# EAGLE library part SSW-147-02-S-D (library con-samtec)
THROUGH-HOLE .025" SQ POST SOCKET Source: Samtec SSW.pdf
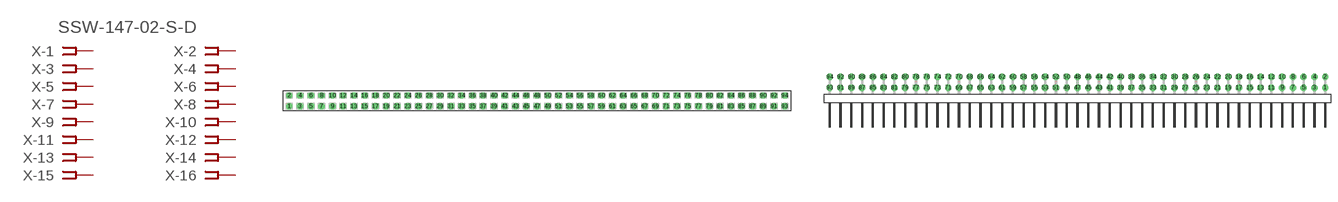
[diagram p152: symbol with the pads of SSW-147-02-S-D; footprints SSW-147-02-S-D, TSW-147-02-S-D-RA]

Designator prefix X; gates -1=FPINV -2=FPIN -3=FPIN -4=FPIN -5=FPIN -6=FPIN -7=FPIN -8=FPIN -9=FPIN -10=FPIN -11=FPIN -12=FPIN -13=FPIN -14=FPIN -15=FPIN -16=FPIN -17=FPIN -18=FPIN -19=FPIN -20=FPIN -21=FPIN -22=FPIN -23=FPIN -24=FPIN -25=FPIN -26=FPIN -27=FPIN -28=FPIN -29=FPIN -30=FPIN -31=FPIN -32=FPIN -33=FPIN -34=FPIN -35=FPIN -36=FPIN -37=FPIN -38=FPIN -39=FPIN -40=FPIN -41=FPIN -42=FPIN -43=FPIN -44=FPIN -45=FPIN -46=FPIN -47=FPIN -48=FPIN -49=FPIN -50=FPIN -51=FPIN -52=FPIN -53=FPIN -54=FPIN -55=FPIN -56=FPIN -57=FPIN -58=FPIN -59=FPIN -60=FPIN -61=FPIN -62=FPIN -63=FPIN -64=FPIN -65=FPIN -66=FPIN -67=FPIN -68=FPIN -69=FPIN -70=FPIN -71=FPIN -72=FPIN -73=FPIN -74=FPIN -75=FPIN -76=FPIN -77=FPIN -78=FPIN -79=FPIN -80=FPIN -81=FPIN -82=FPIN -83=FPIN -84=FPIN -85=FPIN -86=FPIN -87=FPIN -88=FPIN -89=FPIN -90=FPIN -91=FPIN -92=FPIN -93=FPIN -94=FPIN

## SSW-147-02-S-D (OC_FARNELL: unknown; OC_NEWARK: unknown)  [SSW-147-02-S-D]
1  -1:1  pas
2  -2:1  pas
3  -3:1  pas
4  -4:1  pas
5  -5:1  pas
6  -6:1  pas
7  -7:1  pas
8  -8:1  pas
9  -9:1  pas
10  -10:1  pas
11  -11:1  pas
12  -12:1  pas
13  -13:1  pas
14  -14:1  pas
15  -15:1  pas
16  -16:1  pas
17  -17:1  pas
18  -18:1  pas
19  -19:1  pas
20  -20:1  pas
21  -21:1  pas
22  -22:1  pas
23  -23:1  pas
24  -24:1  pas
25  -25:1  pas
26  -26:1  pas
27  -27:1  pas
28  -28:1  pas
29  -29:1  pas
30  -30:1  pas
31  -31:1  pas
32  -32:1  pas
33  -33:1  pas
34  -34:1  pas
35  -35:1  pas
36  -36:1  pas
37  -37:1  pas
38  -38:1  pas
39  -39:1  pas
40  -40:1  pas
41  -41:1  pas
42  -42:1  pas
43  -43:1  pas
44  -44:1  pas
45  -45:1  pas
46  -46:1  pas
47  -47:1  pas
48  -48:1  pas
49  -49:1  pas
50  -50:1  pas
51  -51:1  pas
52  -52:1  pas
53  -53:1  pas
54  -54:1  pas
55  -55:1  pas
56  -56:1  pas
57  -57:1  pas
58  -58:1  pas
59  -59:1  pas
60  -60:1  pas
61  -61:1  pas
62  -62:1  pas
63  -63:1  pas
64  -64:1  pas
65  -65:1  pas
66  -66:1  pas
67  -67:1  pas
68  -68:1  pas
69  -69:1  pas
70  -70:1  pas
71  -71:1  pas
72  -72:1  pas
73  -73:1  pas
74  -74:1  pas
75  -75:1  pas
76  -76:1  pas
77  -77:1  pas
78  -78:1  pas
79  -79:1  pas
80  -80:1  pas
81  -81:1  pas
82  -82:1  pas
83  -83:1  pas
84  -84:1  pas
85  -85:1  pas
86  -86:1  pas
87  -87:1  pas
88  -88:1  pas
89  -89:1  pas
90  -90:1  pas
91  -91:1  pas
92  -92:1  pas
93  -93:1  pas
94  -94:1  pas

## SSW-147-02-S-D-RA (OC_FARNELL: unknown; OC_NEWARK: unknown)  [TSW-147-02-S-D-RA]
Pads as for SSW-147-02-S-D

## Footprint SSW-147-02-S-D (pad centres in mm)
THROUGH-HOLE .025" SQ POST SOCKET Source: Samtec SSW.pdf
drill 1 pad 1.5 octagon: 1 -58.42,-1.27; 2 -58.42,1.27; 3 -55.88,-1.27; 4 -55.88,1.27; 5 -53.34,-1.27; 6 -53.34,1.27; 7 -50.8,-1.27; 8 -50.8,1.27; 9 -48.26,-1.27; 10 -48.26,1.27; 11 -45.72,-1.27; 12 -45.72,1.27; 13 -43.18,-1.27; 14 -43.18,1.27; 15 -40.64,-1.27; 16 -40.64,1.27; 17 -38.1,-1.27; 18 -38.1,1.27; 19 -35.56,-1.27; 20 -35.56,1.27; 21 -33.02,-1.27; 22 -33.02,1.27; 23 -30.48,-1.27; 24 -30.48,1.27; 25 -27.94,-1.27; 26 -27.94,1.27; 27 -25.4,-1.27; 28 -25.4,1.27; 29 -22.86,-1.27; 30 -22.86,1.27; 31 -20.32,-1.27; 32 -20.32,1.27; 33 -17.78,-1.27; 34 -17.78,1.27; 35 -15.24,-1.27; 36 -15.24,1.27; 37 -12.7,-1.27; 38 -12.7,1.27; 39 -10.16,-1.27; 40 -10.16,1.27; 41 -7.62,-1.27; 42 -7.62,1.27; 43 -5.08,-1.27; 44 -5.08,1.27; 45 -2.54,-1.27; 46 -2.54,1.27; 47 0,-1.27; 48 0,1.27; 49 2.54,-1.27; 50 2.54,1.27; 51 5.08,-1.27; 52 5.08,1.27; 53 7.62,-1.27; 54 7.62,1.27; 55 10.16,-1.27; 56 10.16,1.27; 57 12.7,-1.27; 58 12.7,1.27; 59 15.24,-1.27; 60 15.24,1.27; 61 17.78,-1.27; 62 17.78,1.27; 63 20.32,-1.27; 64 20.32,1.27; 65 22.86,-1.27; 66 22.86,1.27; 67 25.4,-1.27; 68 25.4,1.27; 69 27.94,-1.27; 70 27.94,1.27; 71 30.48,-1.27; 72 30.48,1.27; 73 33.02,-1.27; 74 33.02,1.27; 75 35.56,-1.27; 76 35.56,1.27; 77 38.1,-1.27; 78 38.1,1.27; 79 40.64,-1.27; 80 40.64,1.27; 81 43.18,-1.27; 82 43.18,1.27; 83 45.72,-1.27; 84 45.72,1.27; 85 48.26,-1.27; 86 48.26,1.27; 87 50.8,-1.27; 88 50.8,1.27; 89 53.34,-1.27; 90 53.34,1.27; 91 55.88,-1.27; 92 55.88,1.27; 93 58.42,-1.27; 94 58.42,1.27

## Footprint TSW-147-02-S-D-RA (pad centres in mm)
THROUGH-HOLE .025" SQ POST HEADER Source: Samtec TSW.pdf
drill 1 pad 1.5 octagon: 1 58.42,1.524; 2 58.42,4.064; 3 55.88,1.524; 4 55.88,4.064; 5 53.34,1.524; 6 53.34,4.064; 7 50.8,1.524; 8 50.8,4.064; 9 48.26,1.524; 10 48.26,4.064; 11 45.72,1.524; 12 45.72,4.064; 13 43.18,1.524; 14 43.18,4.064; 15 40.64,1.524; 16 40.64,4.064; 17 38.1,1.524; 18 38.1,4.064; 19 35.56,1.524; 20 35.56,4.064; 21 33.02,1.524; 22 33.02,4.064; 23 30.48,1.524; 24 30.48,4.064; 25 27.94,1.524; 26 27.94,4.064; 27 25.4,1.524; 28 25.4,4.064; 29 22.86,1.524; 30 22.86,4.064; 31 20.32,1.524; 32 20.32,4.064; 33 17.78,1.524; 34 17.78,4.064; 35 15.24,1.524; 36 15.24,4.064; 37 12.7,1.524; 38 12.7,4.064; 39 10.16,1.524; 40 10.16,4.064; 41 7.62,1.524; 42 7.62,4.064; 43 5.08,1.524; 44 5.08,4.064; 45 2.54,1.524; 46 2.54,4.064; 47 0,1.524; 48 0,4.064; 49 -2.54,1.524; 50 -2.54,4.064; 51 -5.08,1.524; 52 -5.08,4.064; 53 -7.62,1.524; 54 -7.62,4.064; 55 -10.16,1.524; 56 -10.16,4.064; 57 -12.7,1.524; 58 -12.7,4.064; 59 -15.24,1.524; 60 -15.24,4.064; 61 -17.78,1.524; 62 -17.78,4.064; 63 -20.32,1.524; 64 -20.32,4.064; 65 -22.86,1.524; 66 -22.86,4.064; 67 -25.4,1.524; 68 -25.4,4.064; 69 -27.94,1.524; 70 -27.94,4.064; 71 -30.48,1.524; 72 -30.48,4.064; 73 -33.02,1.524; 74 -33.02,4.064; 75 -35.56,1.524; 76 -35.56,4.064; 77 -38.1,1.524; 78 -38.1,4.064; 79 -40.64,1.524; 80 -40.64,4.064; 81 -43.18,1.524; 82 -43.18,4.064; 83 -45.72,1.524; 84 -45.72,4.064; 85 -48.26,1.524; 86 -48.26,4.064; 87 -50.8,1.524; 88 -50.8,4.064; 89 -53.34,1.524; 90 -53.34,4.064; 91 -55.88,1.524; 92 -55.88,4.064; 93 -58.42,1.524; 94 -58.42,4.064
